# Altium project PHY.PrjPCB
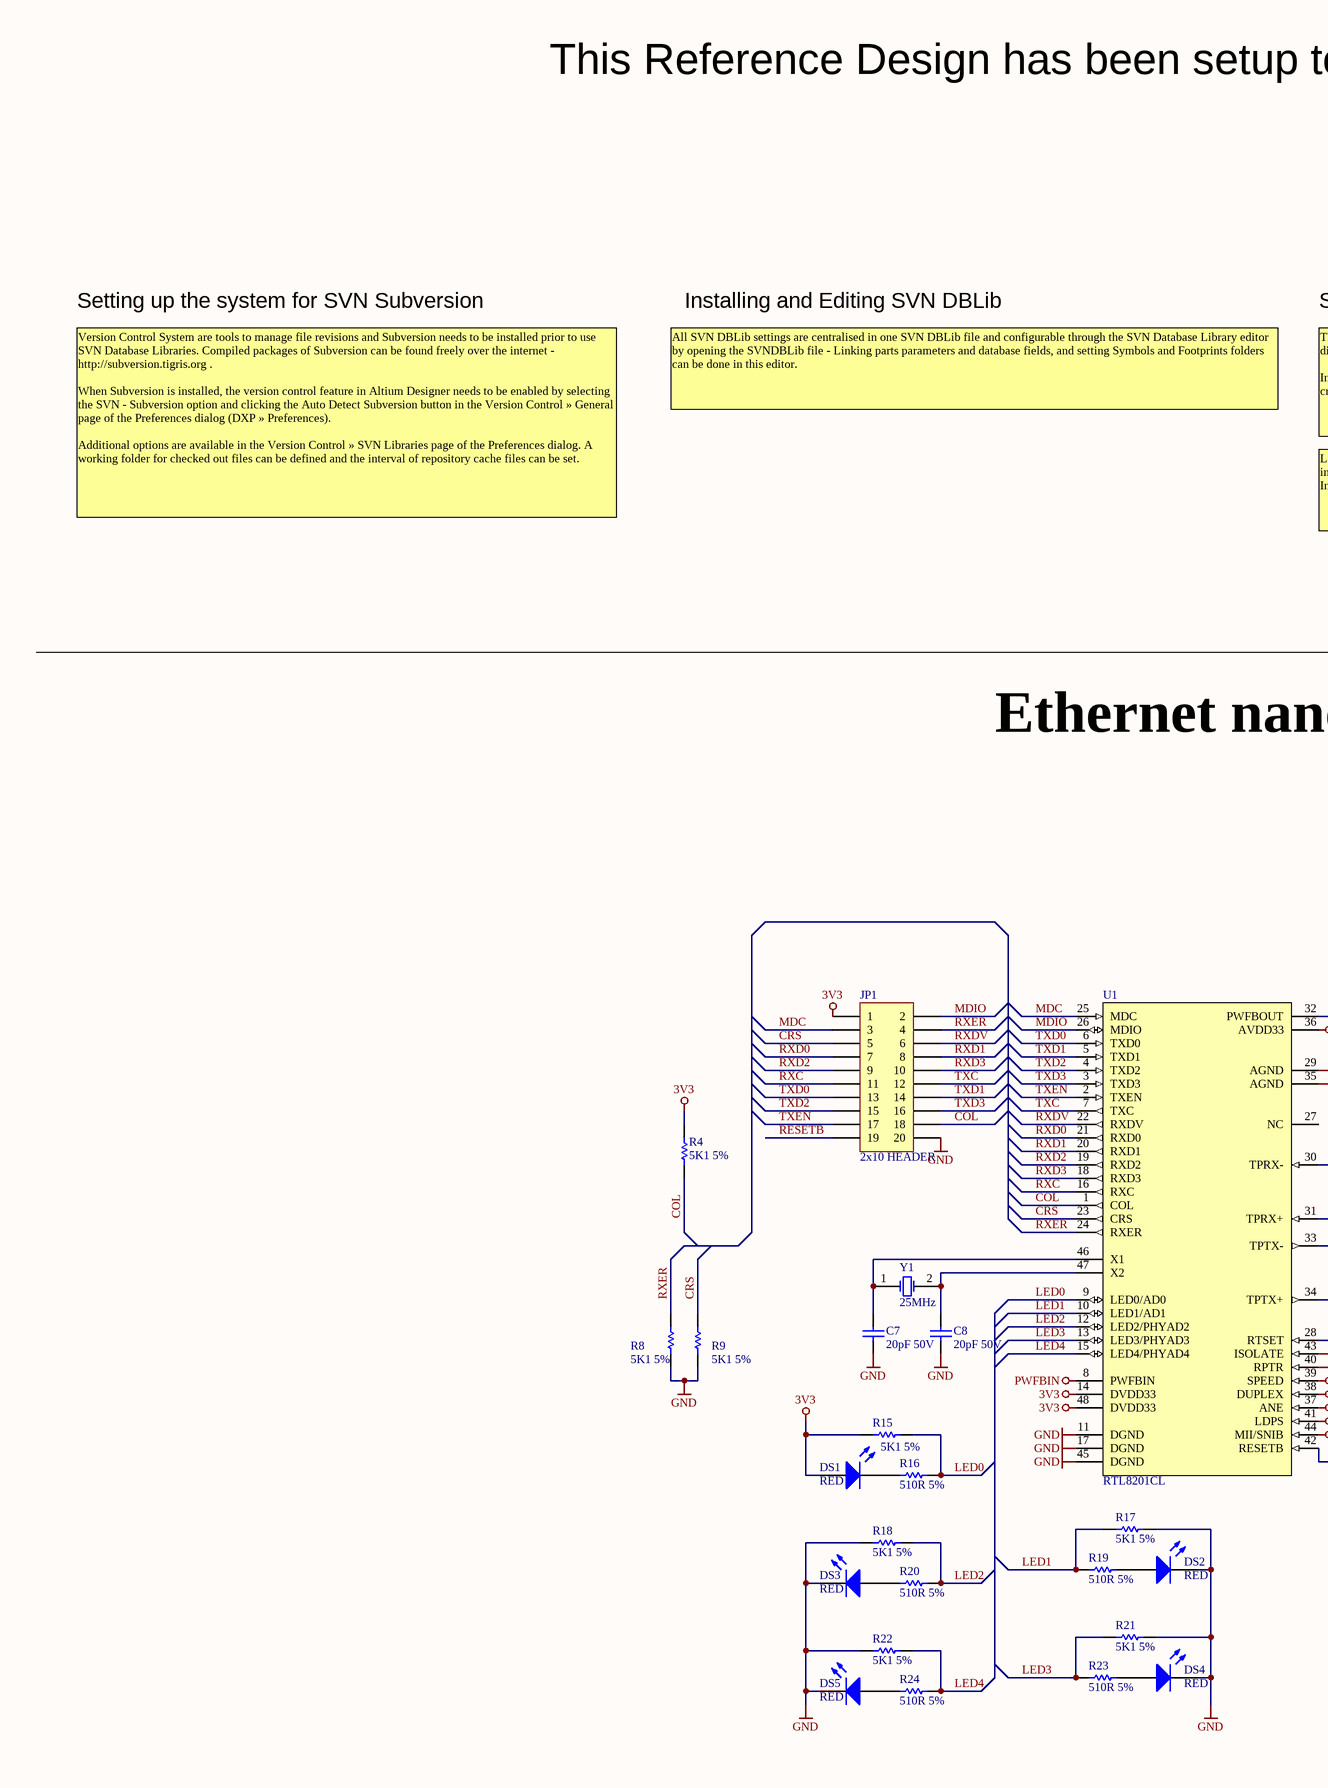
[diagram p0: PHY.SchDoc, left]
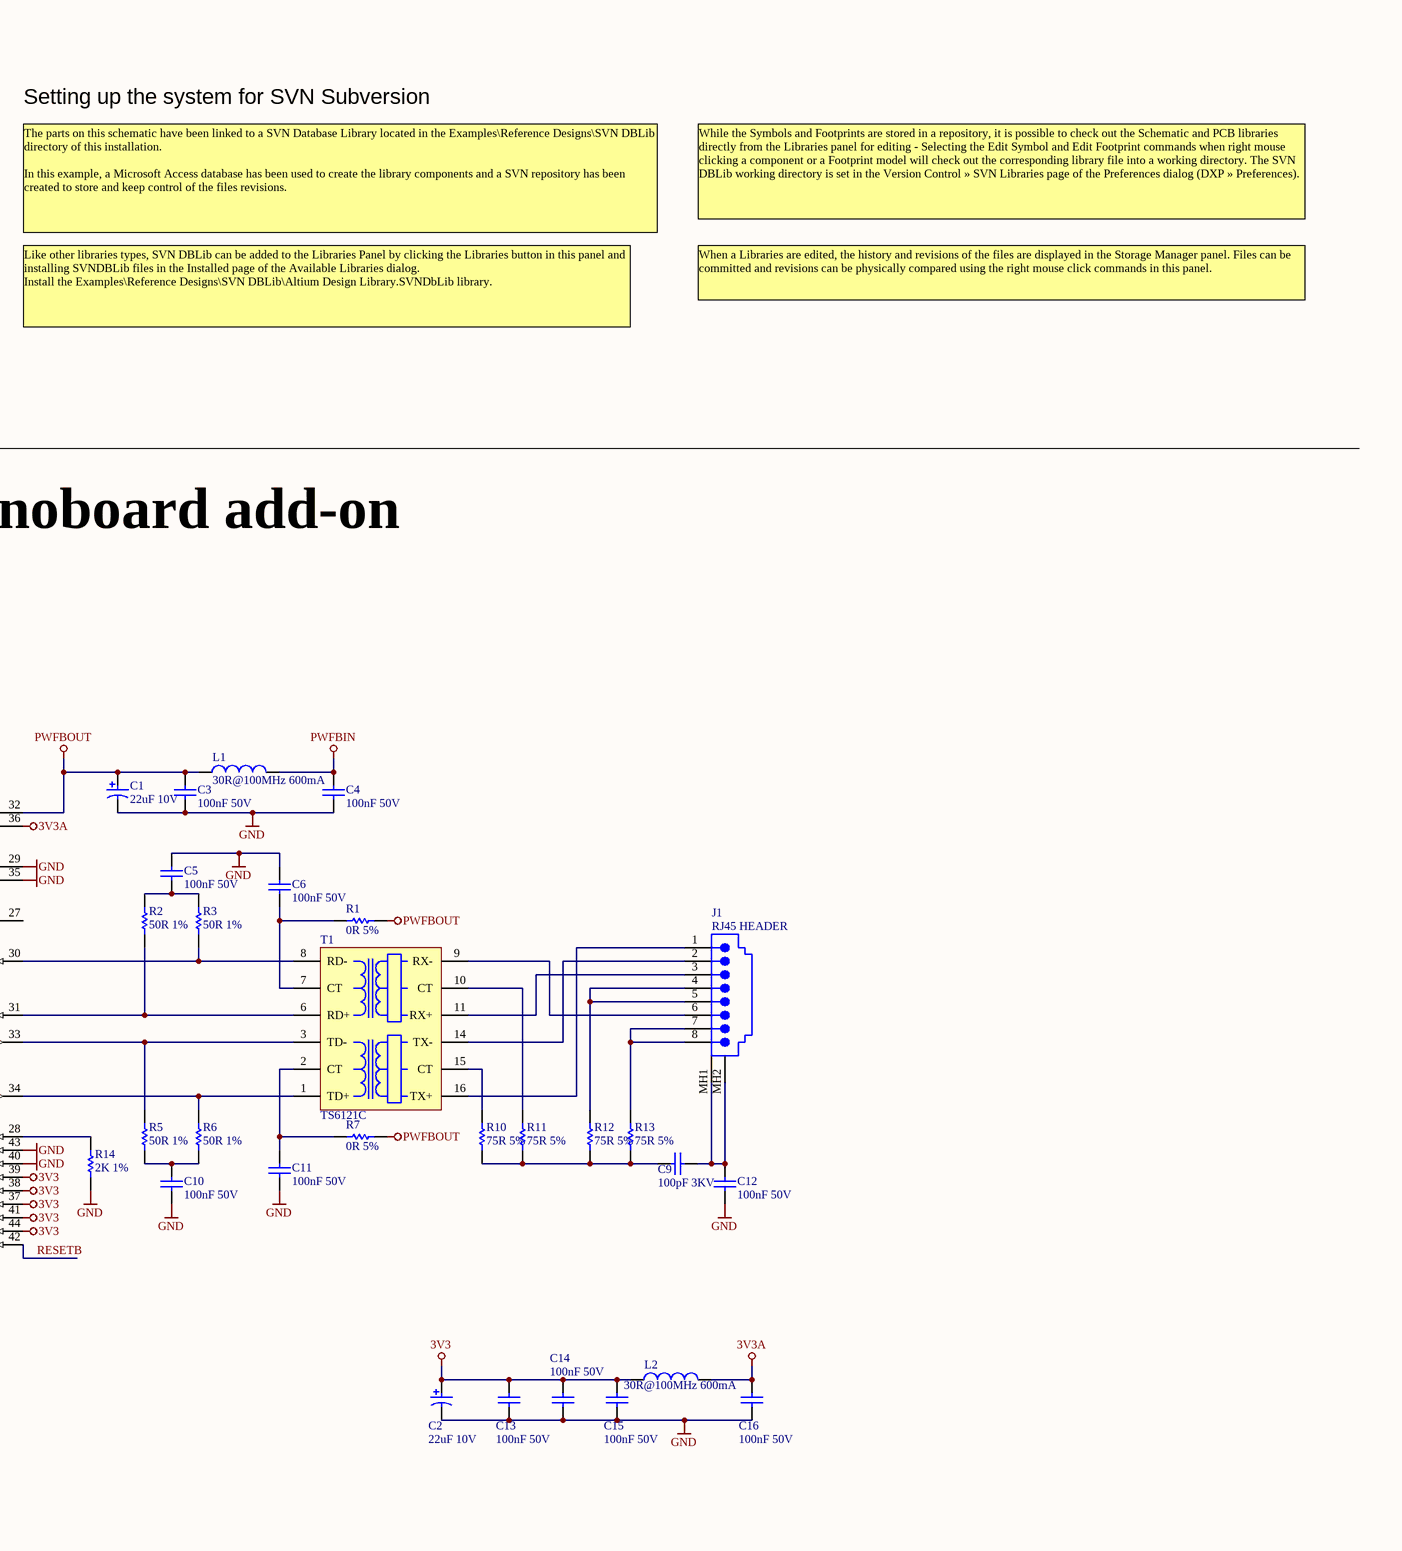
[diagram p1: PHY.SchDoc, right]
1 sheet, 52 parts. Net scope: global (net labels, ports and power ports of the same name join across sheets).
Board file: PHY.PcbDoc

## Sheet PHY.SchDoc: NanoBoard Ethernet Add-On
size C; DocumentNumber: 1; SheetNumber: 1; SheetTotal: 1

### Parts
C1  22uF 10V  [CAPC3528]
C2  22uF 10V  [CAPC3528]
C3  100nF 50V  [CAPC2012]
C4  100nF 50V  [CAPC2012]
C5  100nF 50V  [CAPC2012]
C6  100nF 50V  [CAPC2012]
C7  20pF 50V  [CAPC2012]
C8  20pF 50V  [CAPC2012]
C9  100pF 3KV  [CAPR7_5-3_6x7_5]
C10  100nF 50V  [CAPC2012]
C11  100nF 50V  [CAPC2012]
C12  100nF 50V  [CAPC2012]
C13  100nF 50V  [CAPC2012]
C14  100nF 50V  [CAPC2012]
C15  100nF 50V  [CAPC2012]
C16  100nF 50V  [CAPC2012]
DS1  RED  [LED2013]
DS2  RED  [LED2013]
DS3  RED  [LED2013]
DS4  RED  [LED2013]
DS5  RED  [LED2013]
J1  RJ45 HEADER  [95122-2881]
JP1  2x10 HEADER  [HDR2X10]
L1  30R@100MHz 600mA  [INDC2012]
L2  30R@100MHz 600mA  [INDC2012]
R1  0R 5%  [RESC2012]
R2  50R 1%  [RESC2012]
R3  50R 1%  [RESC2012]
R4  5K1 5%  [RESC2012]
R5  50R 1%  [RESC2012]
R6  50R 1%  [RESC2012]
R7  0R 5%  [RESC2012]
R8  5K1 5%  [RESC2012]
R9  5K1 5%  [RESC2012]
R10  75R 5%  [RESC2012]
R11  75R 5%  [RESC2012]
R12  75R 5%  [RESC2012]
R13  75R 5%  [RESC2012]
R14  2K 1%  [RESC2012]
R15  5K1 5%  [RESC2012]
R16  510R 5%  [RESC2012]
R17  5K1 5%  [RESC2012]
R18  5K1 5%  [RESC2012]
R19  510R 5%  [RESC2012]
R20  510R 5%  [RESC2012]
R21  5K1 5%  [RESC2012]
R22  5K1 5%  [RESC2012]
R23  510R 5%  [RESC2012]
R24  510R 5%  [RESC2012]
T1  TS6121C  [SOIC127P910-16]
U1  RTL8201CL  [TSQFP50P900X900-48]
Y1  25MHz  [XTAL_HC49SMD 20Mhz  +/-30ppm 20pf]

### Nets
3V3: C2.1 C13.2 C14.2 C15.2 DS1.1(A) JP1.1 L2.1 R4.2 R15.2 U1.14(DVDD33) U1.37(ANE) U1.38(DUPLEX) U1.39(SPEED) U1.41(LDPS) U1.44(MII/SNIB) U1.48(DVDD33)
3V3A: C16.2 L2.2 U1.36(AVDD33)
GND: C1.2 C2.2 C3.1 C4.1 C5.2 C6.1 C7.1 C8.1 C10.1 C11.1 C12.1 C13.1 C14.1 C15.1 C16.1 DS2.2(K) DS3.2(K) DS4.2(K) DS5.2(K) JP1.20 R8.1 R9.1 R14.1 R17.1 R18.2 R21.1 R22.2 U1.11(DGND) U1.17(DGND) U1.29(AGND) U1.35(AGND) U1.40(RPTR) U1.43(ISOLATE) U1.45(DGND)
PWFBIN: C4.2 L1.2 U1.8(PWFBIN)
PWFBOUT: C1.1 C3.2 L1.1 R1.2 R7.2 U1.32(PWFBOUT)
COL: JP1.18 R4.1 U1.1(COL)
CRS: JP1.5 R9.2 U1.23(CRS)
LED0: R15.1 R16.1 U1.9(LED0/AD0)
LED1: R17.2 R19.1 U1.10(LED1/AD1)
LED2: R18.1 R20.1 U1.12(LED2/PHYAD2)
LED3: R21.2 R23.1 U1.13(LED3/PHYAD3)
LED4: R22.1 R24.1 U1.15(LED4/PHYAD4)
MDC: JP1.3 U1.25(MDC)
MDIO: JP1.2 U1.26(MDIO)
RESETB: JP1.19 U1.42(RESETB)
RXC: JP1.11 U1.16(RXC)
RXD0: JP1.7 U1.21(RXD0)
RXD1: JP1.8 U1.20(RXD1)
RXD2: JP1.9 U1.19(RXD2)
RXD3: JP1.10 U1.18(RXD3)
RXDV: JP1.6 U1.22(RXDV)
RXER: JP1.4 R8.2 U1.24(RXER)
TXC: JP1.12 U1.7(TXC)
TXD0: JP1.13 U1.6(TXD0)
TXD1: JP1.14 U1.5(TXD1)
TXD2: JP1.15 U1.4(TXD2)
TXD3: JP1.16 U1.3(TXD3)
TXEN: JP1.17 U1.2(TXEN)
NetC5_1: C5.1 R2.2 R3.2
NetC6_2: C6.2 R1.1 T1.7(CT)
NetC7_2: C7.2 U1.46(X1) Y1.1(OSC1)
NetC8_2: C8.2 U1.47(X2) Y1.2(OSC2)
NetC9_1: C9.1 R10.1 R11.1 R12.1 R13.1
NetC9_2: C9.2 C12.2 J1.MH1(Shield) J1.MH2(Shield)
NetC10_2: C10.2 R5.1 R6.1
NetC11_2: C11.2 R7.1 T1.2(CT)
NetDS1_2: DS1.2(K) R16.2
NetDS2_1: DS2.1(A) R19.2
NetDS3_1: DS3.1(A) R20.2
NetDS4_1: DS4.1(A) R23.2
NetDS5_1: DS5.1(A) R24.2
NetJ1_1: J1.1 T1.16(TX+)
NetJ1_2: J1.2 T1.14(TX-)
NetJ1_3: J1.3 T1.11(RX+)
NetJ1_4: J1.4 J1.5 R12.2
NetJ1_6: J1.6 T1.9(RX-)
NetJ1_7: J1.7 J1.8 R13.2
NetR2_1: R2.1 T1.6(RD+) U1.31(TPRX+)
NetR3_1: R3.1 T1.8(RD-) U1.30(TPRX-)
NetR5_2: R5.2 T1.3(TD-) U1.33(TPTX-)
NetR6_2: R6.2 T1.1(TD+) U1.34(TPTX+)
NetR10_2: R10.2 T1.15(CT)
NetR11_2: R11.2 T1.10(CT)
NetR14_2: R14.2 U1.28(RTSET)

Not connected (* = marked no-connect by the designer): U1 27(NC)

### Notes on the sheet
- This Reference Design has been setup to illustrate the use of SVN DBLib in Altium Designer.
- Setting up the system for SVN Subversion
- Installing and Editing SVN DBLib
- All SVN DBLib settings are centralised in one SVN DBLib file and configurable through the SVN Database Library editor by opening the SVNDBLib file - Linking parts parameters and database fields, and setting Symbols and Footprints folders can be done in this editor.
- The parts on this schematic have been linked to a SVN Database Library located in the Examples\Reference Designs\SVN DBLib directory of this installation.
  In this example, a Microsoft Access database has been used to create the library components and a SVN repository has been created to store and keep control of the files revisions.
- While the Symbols and Footprints are stored in a repository, it is possible to check out the Schematic and PCB libraries directly from the Libraries panel for editing - Selecting the Edit Symbol and Edit Footprint commands when right mouse clicking a component or a Footprint model will check out the corresponding library file into a working directory. The SVN DBLib working directory is set in the Version Control » SVN Libraries page of the Preferences dialog (DXP » Preferences).
- Version Control System are tools to manage file revisions and Subversion needs to be installed prior to use SVN Database Libraries. Compiled packages of Subversion can be found freely over the internet - http://subversion.tigris.org .
  When Subversion is installed, the version control feature in Altium Designer needs to be enabled by selecting the SVN - Subversion option and clicking the Auto Detect Subversion button in the Version Control » General page of the Preferences dialog (DXP » Preferences).
  Additional options are available in the Version Control » SVN Libraries page of the Preferences dialog. A working folder for checked out files can be defined and the interval of repository cache files can be set.
- When a Libraries are edited, the history and revisions of the files are displayed in the Storage Manager panel. Files can be committed and revisions can be physically compared using the right mouse click commands in this panel.
- Like other libraries types, SVN DBLib can be added to the Libraries Panel by clicking the Libraries button in this panel and installing SVNDBLib files in the Installed page of the Available Libraries dialog.
  Install the Examples\Reference Designs\SVN DBLib\Altium Design Library.SVNDbLib library.
- Ethernet nanoboard add-on

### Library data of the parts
C1 C2 = CAP-P: Polar Capacitor
C3-C16 = CAP-NP: Capacitor
DS1-DS5 = DIO-LED-1S: Typical GREEN SMD LED Agilent make
J1 = CON-RJ45-10-RA: Right Angle, Standard Profile, External Shield PCB Jack
JP1 = CON-HDR-2x10-STR: Header, 10-Pin, Dual row
L1 L2 = IND-FER: Ferrite Bead
R1-R24 = RES: Resistor
T1 = TS6121C: Bothhand 10/100 BaseT Pulse Transformer
U1 = RTL8201CL: Realtek Ethernet PHY tranceiver
Y1 = CRYS: Surface Mount Crystal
